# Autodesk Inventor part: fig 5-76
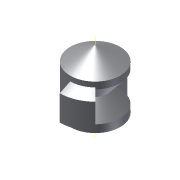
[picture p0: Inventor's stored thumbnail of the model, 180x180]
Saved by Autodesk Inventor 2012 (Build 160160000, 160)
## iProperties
Created: 2004-05
Part Number: fig 5-76
Document SubType Name: Modeling
Designer: CADCIM Technologies
Manufacturer: Standard
Standards Organization: Custom
Density: 1 g/cm^3
Material: Default
Author: CADCIM Technologies
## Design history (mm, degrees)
sketch "Sketch1"
  geometry: L1 (0, -21.51)-(0, 21.51); L2 (0, 21.51)-(-14.639, 13.059); L3 (-14.639, 13.059)-(-14.639, -13.059); L4 (-14.639, -13.059)-(0, -21.51); 2 further points
  constraints: 8 end point, 1 coincident, 1 equal length, 1 midpoint, 1 parallel, 1 vertical, 1 other
  dimensions: "d3" = 120 deg angle of L4 L3
revolve "Revolution1" sketch "Sketch1" stored, may be unused: angle "d0" = 90 deg
workaxis "Work Axis1"
sketch "Sketch2"
  geometry: L1 (-15.658, 10.423)-(-7.144, 0); L2 (-7.144, 0)-(-15.658, -9.738); L3 (-15.658, -9.738)-(-15.658, 10.423); L4 (0, -25.812)-(0, 34.416) reference
  constraints: 6 end point, 1 vertical
revolve "Revolution2" sketch "Sketch2" stored, may be unused: angle "d4" = 140 deg
sketch "Sketch3"
  geometry: L1 (-14.955, 9.983)-(-20.736, 7.191); L2 (-20.736, 7.191)-(-20.736, -7.686); L3 (-20.736, -7.686)-(-15, -10.57); L4 (0, -25.812)-(0, 34.416) reference
  constraints: 6 end point, 1 equal length, 1 vertical
revolve "Revolution4" sketch "Sketch3" stored, may be unused: angle "d9" = 45 deg
body "Solid1"
other parameters: "d10" = 45 deg
